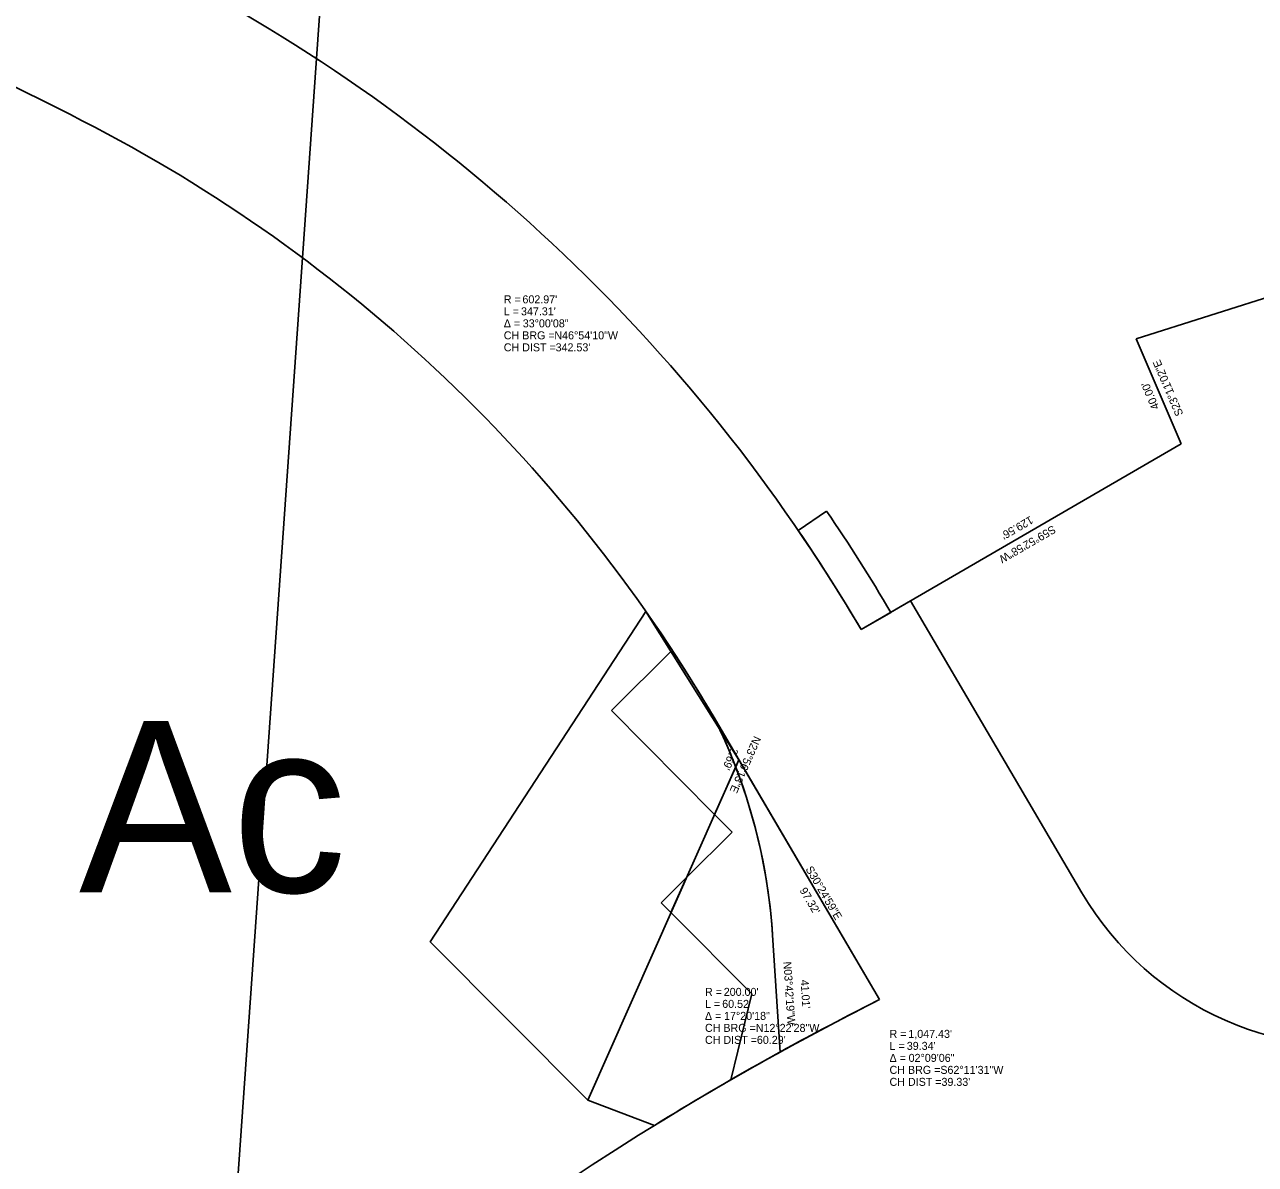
# Model space of a CAD drawing. Extents: x 1926922 to 1928160, y 198652 to 200926.
# Drawn here: x 1927308.2 to 1927738.9, y 199728.7 to 200127.7 of the extents above; entities that cross this region are included whole.
import ezdxf

# ---------------------------------------------------------------- set-up
doc = ezdxf.new("R2010")
doc.units = 0
for name, color, linetype in [('CM_Corridor_Top_Mesh', 7, 'Continuous'), ('Default', 7, 'Continuous'), ('GE_X_Alignment_100_Distances', 7, 'Continuous'), ('GE_X_Alignment_100_Stations', 7, 'Continuous'), ('MD_P_Surface_Ditch', 7, 'Continuous'), ('MD_P_Surface_Finished_Grade', 7, 'Continuous'), ('PV_P_Saw_Cut_Line', 7, 'Continuous'), ('SH_Border', 7, 'Continuous'), ('SH_Major_Grid_Line', 7, 'Continuous')]:
    doc.layers.add(name, color=color, linetype=linetype)

msp = doc.modelspace()

# ---------------------------------------------------------------- linework, layer by layer
at = {"layer": 'CM_Corridor_Top_Mesh'}
for p, q in [((1927054.38, 200231.23), (1927323.97, 200096.26)), ((1927549.12, 199885.64), (1927607.41, 199786.36))]:
    msp.add_line(p, q, dxfattribs=at)
msp.add_lwpolyline([(1927600.94, 199915.88), (1927618.24, 199925.92), (1927678.22, 199823.76)], dxfattribs=at)
for centre, radius, start, end in [((1927080.88, 199610.74), 602.97, 30.4018, 63.404), ((1927080.89, 199610.75), 542.96, 30.4164, 63.4042), ((1927772.34, 199879.02), 109.15, 210.4164, 282.0514), ((1928078.57, 198850.88), 1047.43, 116.73228, 150.49325)]:
    msp.add_arc(centre, radius, start, end, dxfattribs=at)
at = {"layer": 'GE_X_Alignment_100_Distances'}
for p, q in [((1927557.05, 199867.82), (1927558.14, 199870.28)), ((1927558.14, 199870.28), (1927607.41, 199786.36)), ((1927569.97, 199808.93), (1927572.62, 199768.01)), ((1927572.62, 199768.01), (1927569.97, 199808.93))]:
    msp.add_line(p, q, dxfattribs=at)
for centre, radius, start, end in [((1927370.38, 199796.01), 200, 3.7052, 26.4296), ((1927370.38, 199796.01), 200, 3.7052, 21.0436), ((1928078.57, 198850.88), 1047.43, 116.73228, 118.88401)]:
    msp.add_arc(centre, radius, start, end, dxfattribs=at)
at = {"layer": 'GE_X_Alignment_100_Stations'}
for p, q in [((1927578.94, 199950.61), (1927588.85, 199957.38)), ((1927611.32, 199921.9), (1927600.94, 199915.88)), ((1927513.54, 199887.51), (1927534.82, 199908.65)), ((1927549.65, 199851.15), (1927513.54, 199887.51)), ((1927549.65, 199851.15), (1927557.05, 199867.82)), ((1927557.05, 199867.82), (1927549.65, 199851.15)), ((1927555.82, 199844.94), (1927549.65, 199851.15)), ((1927539.85, 199829.08), (1927555.82, 199844.94)), ((1927530.98, 199820.28), (1927539.85, 199829.08)), ((1927534.41, 199816.83), (1927539.85, 199829.08)), ((1927539.85, 199829.08), (1927534.41, 199816.83)), ((1927534.41, 199816.83), (1927530.98, 199820.28)), ((1927562.69, 199788.35), (1927534.41, 199816.83)), ((1927569.97, 199808.93), (1927572.62, 199768.01)), ((1927555.33, 199758.26), (1927562.69, 199788.35))]:
    msp.add_line(p, q, dxfattribs=at)
for centre, radius, start, end in [((1927080.88, 199610.74), 614.97, 30.39625, 34.30934), ((1927080.88, 199610.74), 602.97, 30.4018, 34.30934), ((1927080.89, 199610.75), 542.96, 30.3412, 33.2757), ((1927370.38, 199796.01), 200, 21.0436, 26.4296), ((1927370.38, 199796.01), 200, 3.7052, 21.0436), ((1928078.57, 198850.88), 1047.43, 118.88401, 119.96943)]:
    msp.add_arc(centre, radius, start, end, dxfattribs=at)
at = {"layer": 'MD_P_Surface_Ditch'}
msp.add_line((1927376.1, 199627.83), (1927467.32, 200926.12), dxfattribs=at)
at = {"layer": 'PV_P_Saw_Cut_Line'}
for p, q in [((1927549.48, 199885.02), (1927558.14, 199870.28)), ((1927558.14, 199870.28), (1927557.05, 199867.82))]:
    msp.add_line(p, q, dxfattribs=at)
msp.add_arc((1927370.38, 199796.01), 200, 21.0436, 26.4277, dxfattribs=at)
at = {"layer": 'SH_Major_Grid_Line'}
for p, q in [((1927817.06, 200055.74), (1927697.26, 200017.66)), ((1927697.26, 200017.66), (1927713.01, 199980.89)), ((1927713.01, 199980.89), (1927600.94, 199915.88)), ((1927505.27, 199751.18), (1927558.14, 199870.28)), ((1927558.14, 199870.28), (1927607.41, 199786.36)), ((1927528.62, 199742.32), (1927505.27, 199751.18)), ((1927528.62, 199742.32), (1927528.62, 199742.32))]:
    msp.add_line(p, q, dxfattribs=at)
msp.add_lwpolyline([(1927505.27, 199751.18), (1927450.16, 199806.6), (1927525.66, 199922.17), (1927558.14, 199870.28)], close=True, dxfattribs=at)
for centre, radius, start, end in [((1927080.88, 199610.74), 602.97, 30.4018, 63.404), ((1928078.57, 198850.88), 1047.43, 116.73228, 121.67112)]:
    msp.add_arc(centre, radius, start, end, dxfattribs=at)

# ---------------------------------------------------------------- texts
at = {"layer": 'Default'}
for s, p in [('R = ', (1927546.3, 199787.66)), ("200.00'", (1927552.88, 199787.66)), ('L = ', (1927546.3, 199783.46)), ("60.52'", (1927552.34, 199783.46)), ('Δ = ', (1927546.3, 199779.26)), ('17°20\'18"', (1927552.98, 199779.26)), ('CH BRG = ', (1927546.3, 199775.06)), ('N12°22\'28"W', (1927564.08, 199775.06)), ('R = ', (1927610.9, 199772.96)), ("1,047.43'", (1927617.48, 199772.96)), ('CH DIST = ', (1927546.3, 199770.86)), ("60.29'", (1927564.48, 199770.86)), ('L = ', (1927610.9, 199768.76)), ("39.34'", (1927616.94, 199768.76)), ('Δ = ', (1927610.9, 199764.56)), ('02°09\'06"', (1927617.58, 199764.56)), ('CH BRG = ', (1927610.9, 199760.36)), ('S62°11\'31"W', (1927628.68, 199760.36)), ('CH DIST = ', (1927610.9, 199756.16)), ("39.33'", (1927629.08, 199756.16))]:
    msp.add_text(s, height=2.8, dxfattribs=at).set_placement(p)
at = {"layer": 'MD_P_Surface_Finished_Grade'}
for s, height, p in [('R = ', 2.8, (1927475.89, 200030.09)), ("602.97'", 2.8, (1927482.42, 200030.09)), ('Δ = ', 2.8, (1927475.89, 200021.69)), ('L = ', 2.8, (1927475.89, 200025.89)), ("347.31'", 2.8, (1927481.92, 200025.89)), ('33°00\'08"', 2.8, (1927482.53, 200021.69)), ('CH BRG = ', 2.8, (1927475.89, 200017.49)), ('N46°54\'10"W', 2.8, (1927493.6, 200017.49)), ('CH DIST = ', 2.8, (1927475.89, 200013.29)), ("342.53'", 2.8, (1927494.03, 200013.29)), ('0.197 Ac', 60, (1927104.15, 199823.94))]:
    msp.add_text(s, height=height, dxfattribs=at).set_placement(p)
for s, rotation, p in [('S23°11\'02"E', 113.184, (1927713.77, 199991.32)), ("40.00'", 113.184, (1927705.39, 199993.6)), ("129.56'", 210.1173, (1927660.14, 199955.77)), ('S59°52\'58"W', 210.1173, (1927668.03, 199952.49))]:
    msp.add_text(s, height=2.8, rotation=rotation, dxfattribs=at).set_placement(p)
at = {"layer": 'SH_Border'}
for s, rotation, p in [('N23°56\'13"E', 246.063, (1927563.48, 199878.87)), ("2.69'", 246.063, (1927555.56, 199874.82)), ('S30°24\'59"E', 300.4164, (1927581.4, 199832.07)), ("97.32'", 300.4164, (1927579.29, 199824.6)), ('N03°42\'19"W', 273.7052, (1927573.75, 199799.59)), ("41.01'", 273.7052, (1927579.77, 199793.21))]:
    msp.add_text(s, height=2.8, rotation=rotation, dxfattribs=at).set_placement(p)

doc.saveas('drawing.dxf')
